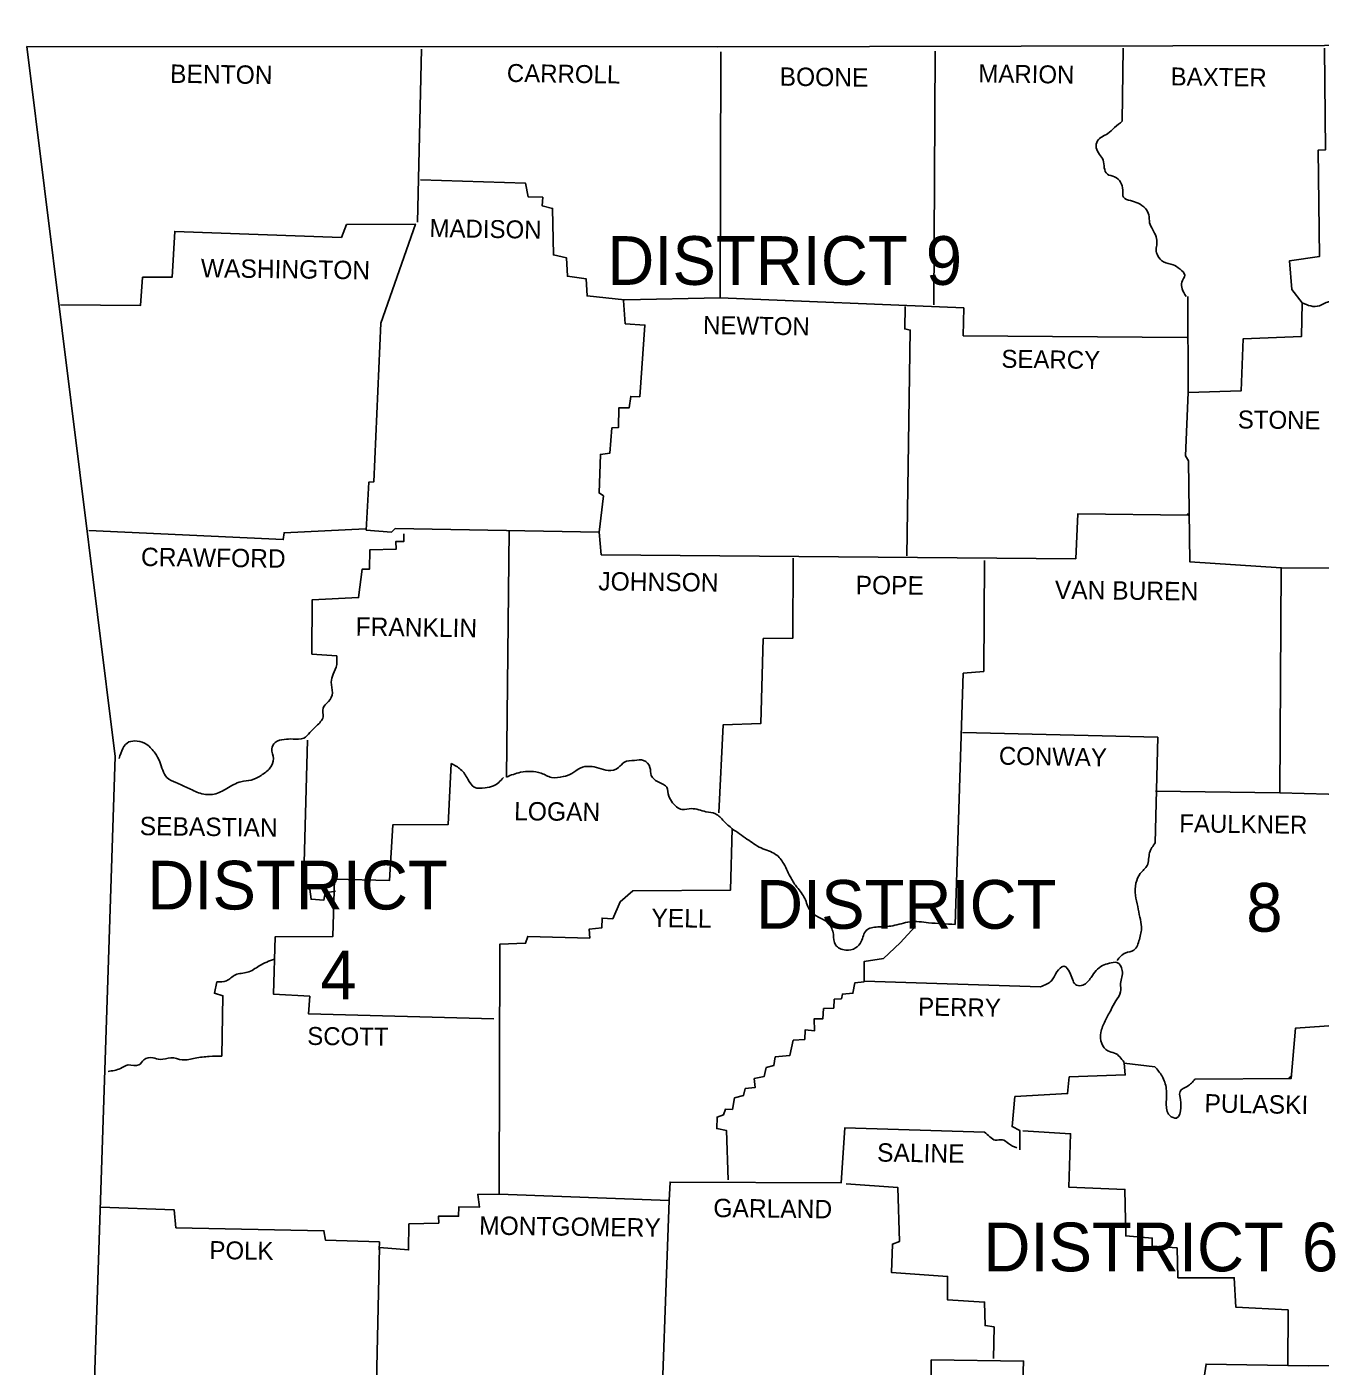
# Model space of a CAD drawing. Extents: x -17742 to 32032, y -17264 to 5867.
# Drawn here: x -17668 to -16002, y 4141 to 5867 of the extents above; entities that cross this region are included whole.
import ezdxf

# ---------------------------------------------------------------- set-up
doc = ezdxf.new("R2010")
doc.units = 0
for name, color, linetype in [('1', 7, 'Continuous'), ('2', 7, 'Continuous'), ('3', 7, 'Continuous')]:
    doc.layers.add(name, color=color, linetype=linetype)

msp = doc.modelspace()

# ---------------------------------------------------------------- linework, layer by layer
at = {"layer": '1'}
for points in [[(-17667.8, 5841.4), (-16777.9, 5840.9), (-15996.9, 5842.5), (-15075.6, 5856.8), (-14648.6, 5866.7)], [(-17667.8, 5841.4), (-17553.9, 4926.7), (-17563.4, 4638.6)], [(-17159.8, 5838.1), (-17164.8, 5615.2)], [(-17160.9, 5669.7), (-17025.5, 5665.3), (-17022.2, 5647.7), (-17003.5, 5647.2), (-17004.1, 5636.1), (-16990.9, 5632.8), (-16989.8, 5572.9), (-16972.7, 5569), (-16971.6, 5545.3), (-16947.4, 5542), (-16946.3, 5520), (-16898.4, 5515.1), (-16775.1, 5517.8), (-16774, 5834.3)], [(-16498.3, 5835.4), (-16500, 5508.5)], [(-16256.1, 5839.2), (-16257.2, 5745.1)], [(-15996.9, 5839.2), (-15995.8, 5708.2), (-16005.2, 5707.7), (-16003.5, 5570.7), (-16042.1, 5565.2), (-16038.8, 5528.3), (-16025.5, 5511.2), (-16026.6, 5467.7), (-16101.5, 5465), (-16104.2, 5397.8), (-16172.5, 5395.6), (-16175.8, 5314.2), (-16171.9, 5307.6), (-16170.3, 5177.7), (-16052.5, 5170), (-16054.2, 4880), (-15960.6, 4877.2), (-15960.6, 4582.2), (-16034.4, 4576.7), (-16039.9, 4511.8), (-16163.7, 4511.2)], [(-17624.3, 5508.5), (-17521.4, 5507.9), (-17518.7, 5544.2), (-17480.7, 5544.2), (-17477.4, 5603.1), (-17262.7, 5595.4), (-17256.1, 5611.9), (-17167.5, 5612.5), (-17212.1, 5484.8), (-17220.9, 5280.6), (-17227.5, 5280.1), (-17230.8, 5218.4), (-17198.4, 5215.7), (-17193.4, 5220.6), (-16930.9, 5215.7), (-16928.1, 5186.5)], [(-16899.5, 5514), (-16897.3, 5484.3), (-16872, 5482.6), (-16878.6, 5390.1), (-16890.2, 5390.7), (-16892.4, 5375.8), (-16905.6, 5375.8), (-16906.1, 5350.5), (-16914.4, 5350), (-16917.1, 5317.5), (-16929.2, 5315.8), (-16930.9, 5266.3), (-16925.4, 5262.5), (-16930.9, 5215.7)], [(-16775.1, 5517.8), (-16461.4, 5504.6), (-16462, 5468.8), (-16174.1, 5466.6)], [(-16536.8, 5506.3), (-16537.4, 5477.6), (-16530.2, 5476), (-16534.6, 5185.4)], [(-16172.5, 5395.6), (-16173, 5519.5)], [(-16928.1, 5186.5), (-16317.2, 5181.6), (-16314.5, 5239.3), (-16172.5, 5237.7)], [(-16174.1, 5238.2), (-16172.5, 5239.9)], [(-17588, 5217.9), (-17337.6, 5206.3), (-17336.5, 5215.1), (-17231.9, 5220.1)], [(-17182.4, 5213.5), (-17182.4, 5203.6), (-17192.8, 5203.6), (-17192.3, 5193.7), (-17225.9, 5193.1), (-17226.4, 5168.3), (-17235.8, 5168.3), (-17240.7, 5131.5), (-17300.2, 5128.7), (-17300.7, 5058.8), (-17268.8, 5056.6)], [(-17046.5, 5217.9), (-17050.3, 4900.3)], [(-16681, 5182.1), (-16681.6, 5079.2), (-16719.5, 5078.6), (-16722.8, 4969.1), (-16771.3, 4967.5), (-16776.8, 4854.1)], [(-16434.5, 5179.4), (-16435.6, 5036.3), (-16462, 5034.1), (-16472.4, 4710.5)], [(-16052.5, 5170), (-15769.6, 5168.3), (-15745.4, 5179.9), (-15747.1, 4964.7), (-15763.6, 4957.6), (-15778.4, 4944.9), (-15783.4, 4940), (-15783.9, 4878.3), (-15963.9, 4878.3)], [(-16463.1, 4957.6), (-16211.6, 4951.5), (-16214.9, 4815.6)], [(-17306.2, 4947.7), (-17311.7, 4758.3), (-17303.5, 4756.1), (-17301.8, 4742.9), (-17285.3, 4741.8), (-17283.7, 4751.2), (-17270.4, 4753.4)], [(-17121.3, 4917.9), (-17125.2, 4839.2), (-17196.7, 4838.7), (-17200.6, 4767.1), (-17271.5, 4768.8), (-17273.7, 4695), (-17348, 4694.5), (-17350.2, 4620.7), (-17303.5, 4618), (-17305.1, 4595.4), (-17066.3, 4588.8)], [(-16214.3, 4882.2), (-16054.2, 4880)], [(-16759.7, 4833.7), (-16761.9, 4754.5), (-16887.4, 4753.9), (-16903.9, 4739.6), (-16913.3, 4717.6), (-16927, 4718.7), (-16927.6, 4706), (-16943.5, 4704.4), (-16943, 4692.8), (-17022.8, 4695), (-17025.5, 4686.2), (-17058.6, 4685.1), (-17059.7, 4363.2), (-17087.2, 4362.6), (-17085, 4346.1), (-17111.4, 4346.7), (-17111.9, 4334.6), (-17137.8, 4334.6), (-17137.3, 4325.8), (-17175.8, 4324.7), (-17176.3, 4291.1), (-17213.8, 4294.4), (-17219.8, 4023.6)], [(-16523.6, 4708.3), (-16543.4, 4686.8), (-16564.9, 4666.4), (-16589.7, 4662.6), (-16589.7, 4636.7), (-16601.8, 4635.1), (-16604, 4621.8), (-16617.7, 4620.7), (-16618.8, 4614.7), (-16628.2, 4614.1), (-16628.7, 4602.6), (-16641.9, 4602), (-16643, 4588.8), (-16654.1, 4588.8), (-16653.5, 4573.4), (-16665.6, 4574.5), (-16666.2, 4562.4), (-16681, 4561.3), (-16685.4, 4541.5), (-16704.1, 4539.8), (-16705.8, 4528.8), (-16715.7, 4526.1), (-16718.4, 4514.5), (-16731.1, 4511.8), (-16730, 4500.2), (-16742.7, 4499.1), (-16744.9, 4490.3), (-16756.4, 4487), (-16759.2, 4472.1), (-16768, 4472.7), (-16770.7, 4465), (-16779, 4462.2), (-16779.5, 4447.4), (-16766.9, 4445.2), (-16764.7, 4381.3)], [(-17563.4, 4638.6), (-17588.2, 3891.9)], [(-17416.8, 4540.9), (-17415.2, 4618.5), (-17426.2, 4621.8), (-17422.9, 4636.7)], [(-16362.4, 4630.1), (-16589.1, 4637.3)], [(-16215.4, 4527.2), (-16255, 4531.6), (-16253.4, 4516.7), (-16325.5, 4514), (-16327.7, 4492.5), (-16395.4, 4488.7), (-16399.2, 4450.1), (-16389.3, 4445.2), (-16389.3, 4419.9)], [(-16042.6, 4512.3), (-16039.9, 4515.1)], [(-16434.5, 4443), (-16614.4, 4448.5), (-16619.4, 4377.5), (-16839.5, 4378.6), (-16840.6, 4354.9)], [(-16385.5, 4444.6), (-16323.8, 4440.8), (-16326, 4372), (-16253.9, 4369.2), (-16252.8, 4309.2), (-16218.7, 4306.5), (-16218.7, 4296), (-16186.8, 4293.8), (-16185.7, 4255.3), (-16113.1, 4255.3), (-16110.9, 4217.3), (-16043.7, 4214), (-16044.3, 4142.5)], [(-16612.8, 4376.4), (-16546.2, 4371.4), (-16544, 4302.1), (-16553.3, 4298.8), (-16554.4, 4261.9), (-16482.3, 4257), (-16482.3, 4226.7), (-16434.5, 4223.9), (-16433.9, 4193.7), (-16422.4, 4192), (-16422.9, 4151.3)], [(-16840.6, 4354.9), (-17059.7, 4363.2)], [(-16840.6, 4354.9), (-16853.3, 4012.1)], [(-17573.1, 4346.1), (-17477.9, 4342.8), (-17475.7, 4319.7), (-17285.3, 4315.8), (-17283.1, 4303.7), (-17213.8, 4301.5), (-17214.3, 4291.1)], [(-15387.7, 4205.8), (-15595.7, 4211.3), (-15596.8, 4143.6), (-16017.8, 4141.9)], [(-16849.4, 4057.7), (-16534.6, 4053.3), (-16528.6, 4105.6), (-16503.8, 4105.6), (-16503.3, 4149.6), (-16384.4, 4148), (-16385.5, 4121.6), (-16354.7, 4119.4), (-16354.7, 4070.9), (-16334.8, 4069.3)], [(-16334.8, 4069.3), (-16304, 4073.7), (-16301.8, 4092.4), (-16283.7, 4095.7), (-16282.6, 4106.7), (-16154.3, 4110.6), (-16149.4, 4144.1), (-16017.8, 4141.9)]]:
    msp.add_lwpolyline(points, dxfattribs=at)
for points in [[(-16257.2, 5745.1), (-16267.2, 5736.9), (-16276, 5729.2), (-16289.2, 5719.8), (-16290.8, 5711), (-16286.4, 5702.2), (-16282, 5695), (-16280.4, 5685.1), (-16276.5, 5676.9), (-16267.2, 5673.6), (-16259.4, 5666.4), (-16256.7, 5656.5), (-16255.6, 5647.2), (-16246.8, 5642.8), (-16236.9, 5639.5), (-16227.5, 5632.8), (-16223.1, 5624.6), (-16222, 5614.1), (-16218.2, 5605.9), (-16213.8, 5596), (-16212.7, 5587.7), (-16213.8, 5579.5), (-16211.6, 5571.8), (-16204.4, 5564.1), (-16191.8, 5560.2), (-16182.9, 5554.7), (-16176.9, 5547), (-16180.7, 5537.6), (-16180.2, 5529.4), (-16175.2, 5519.5)], [(-16025.5, 5511.2), (-16003.5, 5507.4), (-15990.3, 5512.3), (-15981, 5498), (-15976, 5487), (-15967.8, 5471), (-15954.6, 5466.1), (-15944.6, 5457.3), (-15944.6, 5447.9), (-15953.4, 5439.1), (-15960.1, 5430.3), (-15957.9, 5419.9), (-15955.7, 5405.5), (-15955.7, 5391.8), (-15959, 5379.1), (-15961.7, 5367.6), (-15959, 5357.7), (-15948.5, 5359.3), (-15937.5, 5367.6), (-15925.9, 5367.6), (-15914.9, 5361.5), (-15903.4, 5351.1), (-15891.8, 5353.3), (-15882.5, 5356), (-15869.2, 5359.9), (-15859.9, 5354.9), (-15851.6, 5348.3), (-15841.7, 5337.9), (-15832.4, 5331.3), (-15820.3, 5325.2), (-15805.4, 5321.3), (-15791.6, 5312), (-15789.4, 5296), (-15790, 5282.3), (-15791.1, 5265.2), (-15792.2, 5246.5), (-15790.5, 5228.3), (-15784.5, 5216.2), (-15776.8, 5201.9), (-15774.6, 5188.7), (-15775.1, 5167.8)], [(-17268.8, 5056.6), (-17268.8, 5045.1), (-17273.2, 5033), (-17275.9, 5022.5), (-17274.3, 5008.7), (-17279.3, 4997.7), (-17286.4, 4988.9), (-17286.4, 4977.9), (-17294.7, 4966.4), (-17303.5, 4957.6), (-17311.2, 4950.4), (-17324.9, 4949.3), (-17336.5, 4948.8), (-17348, 4944.9), (-17352.4, 4936.6), (-17350.2, 4924), (-17354.7, 4911.9), (-17366.2, 4902.5), (-17378.9, 4896.5), (-17392.1, 4894.3), (-17410.2, 4885.5), (-17426.7, 4878.3), (-17444.4, 4879.4), (-17460.9, 4886.6), (-17475.7, 4893.2), (-17487.3, 4899.8), (-17496.6, 4920.1), (-17502.7, 4931.1), (-17513.2, 4942.2), (-17525.8, 4946.6), (-17536.3, 4945.5), (-17548.9, 4924)], [(-17121.3, 4917.9), (-17109.2, 4910.2), (-17099.8, 4897.6), (-17091.6, 4887.1), (-17077.8, 4886.6), (-17066.8, 4888.8), (-17054.2, 4899.8)], [(-17050.3, 4900.3), (-17032.1, 4906.4), (-17018.9, 4907.5), (-17005.7, 4905.3), (-16992, 4899.8), (-16977.1, 4900.9), (-16966.1, 4904.7), (-16955.1, 4911.9), (-16943, 4914.1), (-16931.4, 4911.9), (-16919.3, 4908.6), (-16906.1, 4912.4), (-16898.4, 4919.6), (-16885.2, 4921.8), (-16873.6, 4921.8), (-16865.4, 4912.4), (-16863.7, 4902.5), (-16853.3, 4893.2), (-16843.9, 4887.1), (-16841.2, 4875.6), (-16836.2, 4867.3), (-16831.3, 4861.8), (-16824.1, 4858.5), (-16812, 4859.6), (-16793.3, 4855.7), (-16781.2, 4853), (-16770.2, 4843.6), (-16759.7, 4833.7)], [(-16759.7, 4833.7), (-16740.5, 4820.5), (-16722.3, 4809), (-16703.6, 4800.7), (-16693.1, 4788.6), (-16683.8, 4769.9), (-16676.1, 4758.3), (-16666.2, 4744), (-16659, 4728.1), (-16647.4, 4719.3), (-16635.3, 4711.6), (-16629.3, 4697.8), (-16626.5, 4684), (-16613.3, 4677.4), (-16600.7, 4680.2), (-16593.5, 4688.4), (-16586.9, 4702.7), (-16572, 4707.2), (-16552.8, 4708.8), (-16530.8, 4713.8), (-16506.6, 4712.7), (-16472.4, 4710.5)], [(-16214.9, 4815.6), (-16222, 4802.9), (-16225.3, 4786.4), (-16234.1, 4775.9), (-16239.6, 4763.8), (-16240.2, 4747.9), (-16237.4, 4733.6), (-16234.7, 4719.8), (-16232.5, 4707.2), (-16235.2, 4691.2), (-16242.4, 4677.4), (-16253.4, 4673.6), (-16263.8, 4664.2)], [(-17422.9, 4636.7), (-17410.8, 4637.8), (-17399.2, 4645.5), (-17383.8, 4648.8), (-17368.4, 4657.1), (-17349.1, 4665.9)], [(-16362.4, 4630.1), (-16348.6, 4637.8), (-16341.4, 4649.4), (-16332.6, 4656.5), (-16323.8, 4646.6), (-16316.1, 4632.3), (-16307.9, 4632.3), (-16297.4, 4642.2), (-16290.8, 4651), (-16282.6, 4657.6), (-16273.8, 4660.4), (-16264.4, 4661.5), (-16257.2, 4651), (-16259.4, 4634.5), (-16259.4, 4623.5), (-16265.5, 4611.9), (-16272.1, 4599.8), (-16279.3, 4586.1), (-16284.8, 4571.2), (-16283.7, 4556.9), (-16276, 4547.5), (-16267.2, 4544.8), (-16255, 4532.7)], [(-17416.8, 4540.9), (-17432.8, 4540.4), (-17451, 4538.2), (-17467.5, 4536), (-17482.3, 4538.7), (-17496.1, 4536.5), (-17505.4, 4538.7), (-17517, 4536), (-17523.6, 4529.4), (-17537.4, 4529.4), (-17547.3, 4525), (-17563.2, 4521.1)], [(-16215.4, 4527.2), (-16206.1, 4515.1), (-16200.6, 4498.6), (-16200.6, 4479.9), (-16196.2, 4464.4), (-16187.4, 4461.1), (-16181.8, 4474.4), (-16182.9, 4487.6), (-16182.9, 4495.3), (-16173.6, 4501.9), (-16163.7, 4511.2)], [(-16393.2, 4422.6), (-16403.6, 4428.1), (-16411.9, 4433.1), (-16420.7, 4432.5), (-16427.9, 4436.9), (-16434.5, 4443)]]:
    msp.add_spline(points, degree=3, dxfattribs=at)

# ---------------------------------------------------------------- texts
at = {"layer": '2'}
for s, height, rotation, p in [('BENTON', 23.67, 359.2527, (-17483.4, 5794.6)), ('CARROLL', 23.11, 359.1481, (-17049.8, 5795.8)), ('BOONE', 23.67, 359.4001, (-16698.6, 5790.8)), ('MARION', 23.11, 359.1854, (-16442.7, 5795.2)), ('BAXTER', 23.11, 359.2559, (-16195.1, 5791.3)), ('MADISON', 23.11, 359.0906, (-17149.4, 5596)), ('WASHINGTON', 23.66, 359.232, (-17443.8, 5544.2)), ('NEWTON', 23.11, 359.2717, (-16797.1, 5471)), ('SEARCY', 23.11, 359.2527, (-16413, 5427.6)), ('STONE', 23.11, 359.4001, (-16108.6, 5349.4)), ('CRAWFORD', 23.66, 359.2771, (-17520.9, 5172.2)), ('JOHNSON', 23.67, 359.3514, (-16932, 5140.8)), ('POPE', 23.67, 359.6155, (-16600.7, 5135.9)), ('VAN BUREN', 23.67, 359.3508, (-16344.2, 5129.8)), ('FRANKLIN', 23.67, 359.1815, (-17244.6, 5082.5)), ('CONWAY', 23.11, 359.0371, (-16416.3, 4916.3)), ('LOGAN', 23.67, 359.3969, (-17040.4, 4844.7)), ('SEBASTIAN', 23.66, 359.2816, (-17522.5, 4825.5)), ('FAULKNER', 23.11, 359.2486, (-16184, 4829.3)), ('YELL', 23.67, 359.1987, (-16863.7, 4707.2)), ('PERRY', 23.11, 359.0858, (-16520.3, 4593.2)), ('SCOTT', 23.11, 359.4063, (-17306.8, 4555.3)), ('PULASKI', 23.67, 359.053, (-16151.6, 4468.3)), ('SALINE', 23.67, 359.1491, (-16573.1, 4405)), ('GARLAND', 23.67, 359.3658, (-16783.9, 4333.5)), ('MONTGOMERY', 23.67, 359.2944, (-17085.5, 4310.9)), ('POLK', 23.11, 359.2152, (-17432.8, 4279.5))]:
    msp.add_text(s, height=height, rotation=rotation, dxfattribs=at).set_placement(p)
at = {"layer": '3'}
for s, height, p in [('DISTRICT 9', 62.74, (-16920.4, 5534.3)), ('DISTRICT', 62.74, (-17512.6, 4729.7)), ('DISTRICT', 62.74, (-16728.9, 4704.9)), ('8', 62.7, (-16097.6, 4701.1)), ('4', 62.7, (-17289.7, 4614.1)), ('DISTRICT 6', 62.74, (-16436.1, 4263.6))]:
    msp.add_text(s, height=height, dxfattribs=at).set_placement(p)

doc.saveas('drawing.dxf')
